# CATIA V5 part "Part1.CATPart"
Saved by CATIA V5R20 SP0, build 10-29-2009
Part number: Part1
Bounding box of the stored display mesh (mm): x -5 to 10, y 0 to 100, z -5 to 5
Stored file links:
  E:\Ehsan\CATIA\CATIA Course\CATIA Course\Basic\CATIA Tamrin\Assembly\1\Part1.CATPart
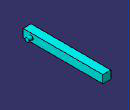
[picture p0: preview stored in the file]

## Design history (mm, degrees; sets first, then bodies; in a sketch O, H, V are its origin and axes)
Body1 (main body)
  Sketch1 on zx-plane, origin (0, 0, 0), H (-1, 0, 0), V (0, 0, 1)
    line L1 (5, 5) -> (5, -5)
    line L2 (5, -5) -> (-5, -5)
    line L3 (-5, -5) -> (-5, 5)
    line L4 (-5, 5) -> (5, 5)
    distance L2 L4 = 10
    distance L1 L3 = 10
    vertical: L1 V, L3 V
    horizontal: L2 H, L4 H
    equidistance: L1 L3 O, L2 L4 O
  Pad1: profile Sketch1, direction (0, 1, 0), length 100
  Sketch2 on face of Pad1 from Sketch1.L3, origin (5, 0, 0), H (0, 1, 0), V (0, 0, 1)
    circle A1 centre (10, 0) radius 2.5
    point P1 (10, 0)
    distance P1 V = 10
    distance P1 H = 0
    radius A1 = 2.5
  Pad2: profile Sketch2, direction (1, 0, 0), length 5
